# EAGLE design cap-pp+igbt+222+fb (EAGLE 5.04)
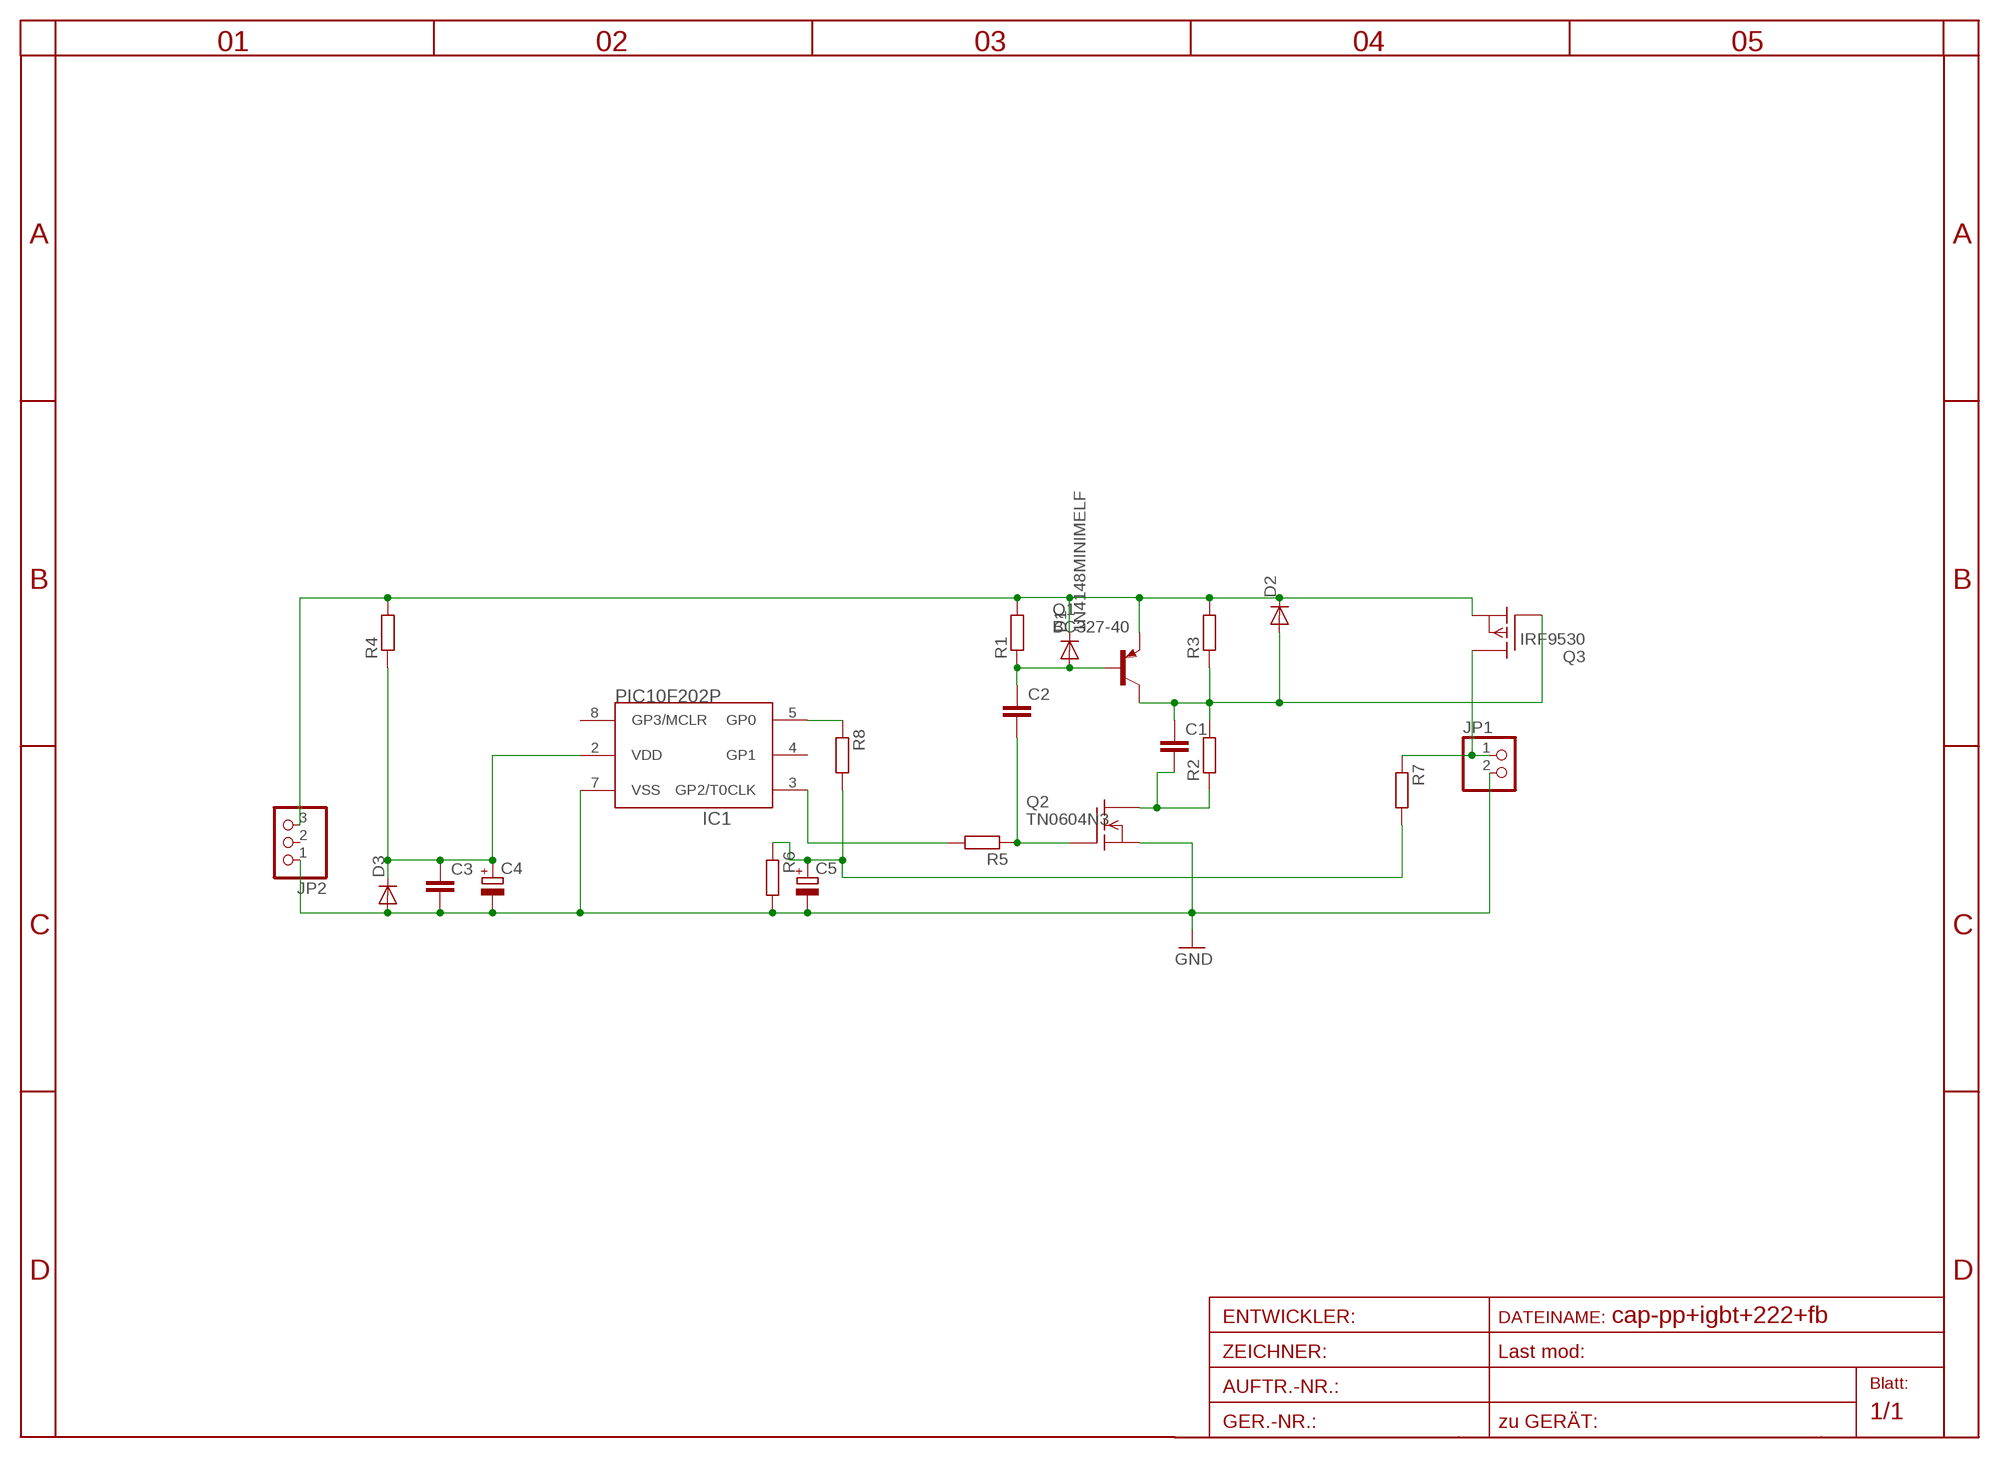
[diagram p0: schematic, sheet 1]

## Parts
C1  C-EU025_050-025X075  [C025_050-025X075]
C2  C-EU025_050-025X075  [C025_050-025X075]
C3  C-EU025_050-025X075  [C025_050-025X075]
C4  CPOL-EU5-13  [2,5-5-FLAT]
C5  CPOL-EU5-13  [2,5-5-FLAT]
D1  1N4148MINIMELF  [MINIMELF]
D2  DIODE-D-5  [D-5]
D3  DIODE-D-2.5  [D-2.5]
IC1  PIC10F202P  [DIL8]
JP1  PINHD-1X2  [1X02]
JP2  PINHD-1X3  [1X03]
Q1  BC327-40  [TO92-EBC]
Q2  TN0604N3  [TO-92]
Q3  IRF9530  [TO220]
R1  R-EU_0204/2V  [0204V]
R2  R-EU_0204/2V  [0204V]
R3  R-EU_0204/2V  [0204V]
R4  R-EU_0204/2V  [0204V]
R5  R-EU_0204/2V  [0204V]
R6  R-EU_0204/2V  [0204V]
R7  R-EU_0204/2V  [0204V]
R8  R-EU_0204/2V  [0204V]

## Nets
BB: C2.2 Q2.2(G) R5.1
DRAIN: JP1.1 Q3.2(D) R7.1
GND: C3.2 C4.- C5.- D3.A IC1.7(VSS) JP1.2 JP2.1 Q2.1(S) R6.2
MPOINT: C5.+ R6.1 R7.2 R8.2
N$1: C1.2 Q2.3(D) R2.1
N$3: IC1.3(GP2/T0CLK) R5.2
N$4: C3.1 C4.+ D3.C IC1.2(VDD) R4.1
N$5: IC1.5(GP0) R8.1
OUT: C1.1 D2.A Q1.C Q3.1(G) R2.2 R3.1
TB: C2.1 D1.A Q1.B R1.1
V+: D1.C D2.C JP2.3 Q1.E Q3.3(S) R1.2 R3.2 R4.2
Unconnected: IC1.4(GP1) IC1.8(GP3/MCLR) JP2.2

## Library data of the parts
C1-C3 = rcl-2:C-EU: CAPACITOR, European symbol
C4 C5 = rcl-2:CPOL-EU: POLARIZED CAPACITOR, European symbol
D1 = diode-1:1N4148: DIODE
D2 D3 = diode-1:DIODE-: DIODE
IC1 = microchip-5:PIC10F20*: uPC nW 0,25/0,5k Program Flash memory
JP1 = pinhead:PINHD-1X2: PIN HEADER
JP2 = pinhead:PINHD-1X3: PIN HEADER
Q1 = transistor-pnp:BC327*: PNP Transistror
Q2 = transistor-fet:TN0604N3: N-Channel Enhancement MOSFET 40V; 4A; 0,75Ohm
Q3 = transistor-fet:IRF9530: P-Channel Enhancement MOSFET (HEXFET); -100V; -12A; 0,3Ohm
R1-R8 = rcl-2:R-EU_: RESISTOR, European symbol

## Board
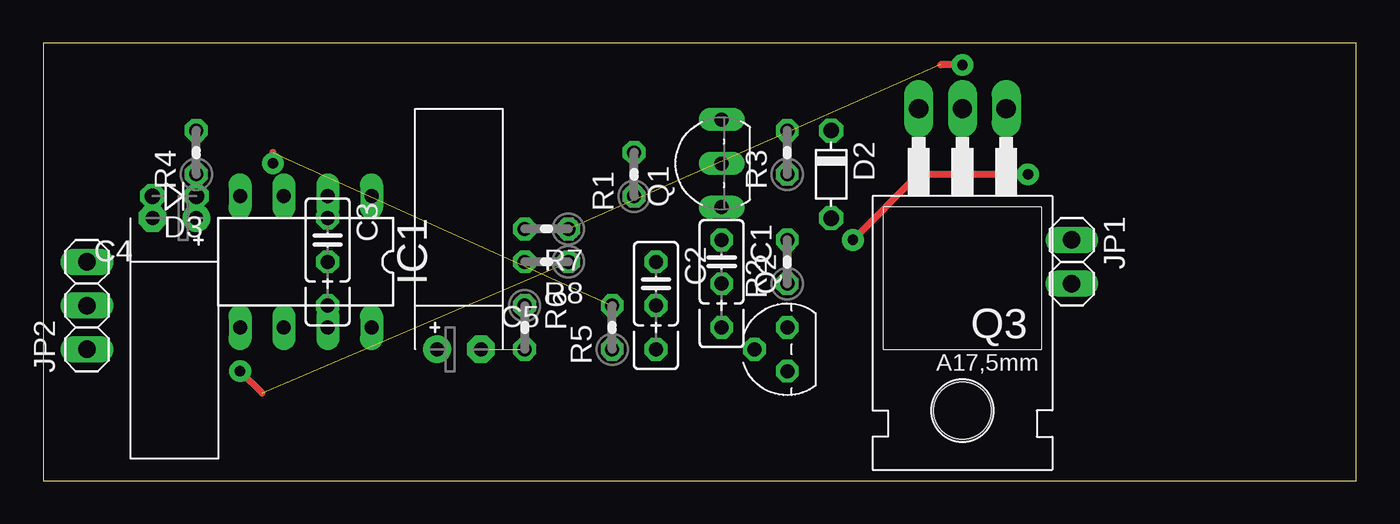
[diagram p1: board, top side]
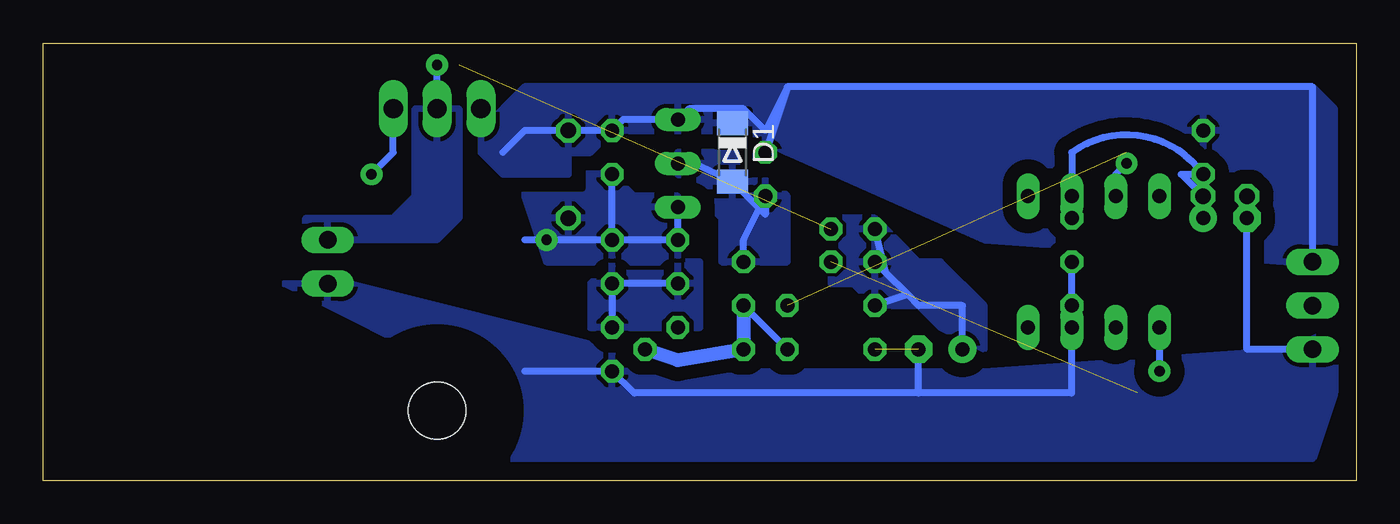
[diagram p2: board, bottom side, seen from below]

Size 76.2 x 25.4 mm. Coordinates in mm from the lower left corner, seen from the top.
Outline: 0,0 76.2,0 76.2,25.4 0,25.4 0,0
Copper layers (1*16): Top 0.035mm / dielectric 1.5mm / Bottom 0.035mm
Design rules "default": minimum track width 10mil, minimum drill 24mil, track to track 8mil, track to pad 8mil, pad to pad 8mil, via to via 8mil, smd to smd 8mil, copper to edge 40mil, drill to drill 8mil, minimum pad ring 10mil, minimum via ring 8mil, stop-mask expansion 4mil, vias tented up to drill 0mil, thermal gap 10mil

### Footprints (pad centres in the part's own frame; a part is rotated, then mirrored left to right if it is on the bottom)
C025_050-025X075 = drill 0.813 octagon: 1 -1.27,0; 2 1.27,0; 3 3.81,0
2,5-5-FLAT = drill 0.813 pad 1.6 round: + -1.27,0 | drill 0.813 pad 1.6 octagon: - 1.27,0
MINIMELF = smd 1.4 x 1.8: A 1.7,0; C -1.7,0
D-5 = drill 0.9 octagon: A 2.54,0; C -2.54,0
D-2.5 = drill 0.9 octagon: A 1.27,0; C -1.27,0
DIL8 = drill 0.813 long: 1 -3.81,-3.81; 2 -1.27,-3.81; 3 1.27,-3.81; 4 3.81,-3.81; 5 3.81,3.81; 6 1.27,3.81; 7 -1.27,3.81; 8 -3.81,3.81
1X02 = drill 1.016 long: 1 -1.27,0; 2 1.27,0
1X03 = drill 1.016 long: 1 -2.54,0; 2 0,0; 3 2.54,0
TO92-EBC = drill 0.813 long: B 0,-1.27; C -2.54,-1.27; E 2.54,-1.27
TO-92 = drill 0.813 octagon: 1 -1.27,0; 2 0,1.905; 3 1.27,0
TO220 = drill 1.118 long: 1 -2.54,-6.35; 2 0,-6.35; 3 2.54,-6.35 | hole 3.302: 0,11.176
0204V = drill 0.813 octagon: 1 -1.27,0; 2 1.27,0

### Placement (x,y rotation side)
C1  39.37,12.7 270 top
C2  35.56,11.43 270 top
C3  16.51,13.97 270 top
C4  7.62,15.24 180 top
C5  24.13,7.62 0 top
D1  36.2,19.05 270 bottom
D2  45.72,17.78 270 top
D3  7.62,16.51 180 top
IC1  15.24,12.7 180 top
JP1  59.69,12.7 270 top
JP2  2.54,10.16 90 top
Q1  38.1,18.41 90 top
Q2  43.18,7.62 90 top
Q3  53.34,15.24 180 top
R1  34.29,17.78 90 top
R2  43.18,12.7 90 top
R3  43.18,19.05 90 top
R4  8.89,19.05 90 top
R5  33.02,8.89 90 top
R6  27.94,8.89 270 top
R7  29.21,14.61 180 top
R8  29.21,12.7 180 top

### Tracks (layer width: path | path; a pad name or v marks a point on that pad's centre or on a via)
BB
  Bottom 0.406: R5.1 C2.2
  Bottom 0.813: Q2.2 39.37,6.99 35.56,7.62 C2.2
DRAIN  (via drill 0.6 pad 1.27)  (1 unrouted)
  Top 0.406: v53.34,24.13 52.07,24.13
  Bottom 0.406: Q3.2 v53.34,24.13
  pour Bottom: 52.07,21.59 52.07,15.24 53.34,13.97 60.96,13.97 60.96,15.24 55.88,15.24 54.61,16.51 54.61,21.59
GND  (1 unrouted)
  Bottom 0.406: 48.26,6.35 Q2.1 41.91,5.08 25.4,5.08 | D3.A C4.- 6.35,7.62 JP2.1 | C3.2 IC1.7 16.51,5.08 25.4,5.08 | 25.4,5.08 C5.-
  pour Bottom (isolate 0.813): 1.27,8.89 1.27,5.08 2.54,1.27 49.53,1.27 52.07,6.35 62.23,11.43 58.42,11.43 43.18,7.62 41.91,6.35 21.59,6.35 3.81,7.62
MPOINT
  Bottom 0.406: C5.+ 22.86,10.16 25.4,10.16 26.04,10.79 | 26.04,10.79 27.3,12.06 | 27.3,12.06 R7.2 | 26.04,10.79 R6.1 | 27.3,12.06 R8.2
  pour Bottom: 21.59,7.62 21.59,10.16 24.13,12.7 25.4,12.7 26.67,13.97 27.94,15.24 30.48,15.24 30.48,11.43 29.21,11.43 27.94,10.16 25.4,10.16 24.13,8.89
N$1
  Bottom 0.406: C1.2 R2.1 Q2.3
  pour Bottom (isolate 0.254, rank 3): 38.1,12.7 43.18,12.7 44.45,11.43 44.45,8.89 38.1,8.89
N$3  (via drill 0.6 pad 1.27)  (1 unrouted)
  Top 0.406: v13.34,18.41 13.34,19.05
  Bottom 0.406: IC1.3 13.97,17.78 v13.34,18.41
N$4
  Bottom 0.406: C4.+ D3.C 10.16,17.78 R4.1 arc-90 16.51,19.05 IC1.2 C3.1
N$5  (via drill 0.6 pad 1.27)  (1 unrouted)
  Top 0.406: v11.43,6.35 12.7,5.08
  Bottom 0.406: IC1.5 v11.43,6.35
OUT  (via drill 0.6 pad 1.27)
  Top 0.406: v57.15,17.78 50.8,17.78 v46.99,13.97
  Bottom 0.406: R2.2 v46.99,13.97 48.26,13.97 | R2.2 C1.1 Q1.C | R2.2 R3.1 | Q3.1 55.88,19.05 v57.15,17.78
  pour Bottom (isolate 0.813, rank 2): 39.37,16.51 41.91,16.51 43.18,17.78 48.26,17.78 48.26,16.51 46.99,12.7 39.37,12.7
TB
  Bottom 0.406: C2.1 35.56,13.97 R1.1 34.29,15.45 D1.A 38.94,18.62 39.16,18.62 Q1.B
  pour Bottom (isolate 0.813, rank 3): 36.83,12.7 33.02,12.7 33.02,16.51 35.56,19.05 39.37,19.05 39.37,17.78 36.83,15.24
V+
  Bottom 0.406: JP2.3 2.54,22.86 33.02,22.86 | 33.02,22.86 34.29,20.32 35.56,21.59 36.83,21.59 | 36.83,21.59 38.73,21.59 Q1.E 42.55,20.95 R3.2 48.26,20.32 49.53,19.05 | D1.C 36.2,20.95 36.83,21.59 | 33.02,22.86 R1.2
  pour Bottom (isolate 0.813): 1.27,12.7 1.27,21.59 2.54,22.86 48.26,22.86 50.8,20.32 50.8,19.05 49.53,17.78 45.72,17.78 45.72,19.05 44.45,19.05 43.18,20.32 35.56,20.32 33.02,19.05 21.59,13.97 3.81,12.7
